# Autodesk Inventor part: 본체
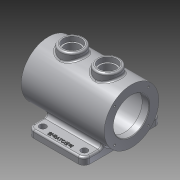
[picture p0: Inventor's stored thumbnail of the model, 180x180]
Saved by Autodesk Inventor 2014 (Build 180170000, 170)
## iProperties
Created: 2014-12
Part Number: 본체
Material: 알루미늄 6061
Document SubType Name: Modeling
Designer: Owner
Density: 2.71 g/cm^3
Appearance: 알루미늄 - 평지
Mass: 1293.91 g
Surface Area: 1040.15 cm^2
Volume: 477.456 cm^3
Author: Owner
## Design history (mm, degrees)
sketch "스케치1"
  geometry: L1 (-47.5, 65)-(47.5, 65); L2 (47.5, 65)-(47.5, -65); L3 (47.5, -65)-(-47.5, -65); L4 (-47.5, -65)-(-47.5, 65); 3 further points
  constraints: 8 end point, 2 midpoint, 2 parallel, 1 horizontal, 1 horizontal alignment, 1 perpendicular, 1 vertical alignment
  dimensions: "d0" = 95 distance of L1.start L1.end; "d1" = 130 distance of L1.end L2.end
extrude "돌출1" new body sketch "스케치1" distance "d2" = 12; taper "d3" = 0 deg
node "작업 평면1"
sketch "스케치2"
  geometry: L1 (0, 130)-(0, 0) reference; C1 r 46 at (-50, 65); 1 further point
  constraints: 1 centre point, 1 horizontal alignment
  dimensions: "d5" = 50 distance from line of L1 C1.centre; "d6" = 92 diameter of C1
extrude "돌출2" join sketch "스케치2" distance "d7" = 140; taper "d8" = 0 deg
node "작업 평면2"
sketch "스케치3"
  geometry: L1 (62.5, 46)-(62.5, -46) reference; C1 r 20 at (22.5, 0); C2 r 20 at (-37.5, 0); 1 further point
  constraints: 2 centre point, 2 horizontal alignment
  dimensions: "d10" = 40 distance from line of L1 C1.centre; "d11" = 60 distance of C2.centre C1.centre; "d12" = 40 diameter of C1; "d13" = 40 diameter of C2
extrude "돌출3" join sketch "스케치3" stored distance "d14" = 140; taper "d15" = 0 deg
hole "구멍1" diameter "d18" = 60; stored, may be unused: countersink angle "d22" = 90 deg, drill point angle "d24" = 0 deg; dims "d16" = 10, "d17" = 10, "d19" = 6, "d20" = 4, "d21" = 2, "d23" = 12
hole "구멍2" diameter "d27" = 75; stored, may be unused: countersink angle "d31" = 90 deg, drill point angle "d33" = 0 deg; dims "d25" = 10, "d26" = 10, "d28" = 6, "d29" = 4, "d30" = 2, "d32" = 116
hole "구멍3" diameter "d36" = 60; stored, may be unused: countersink angle "d40" = 90 deg, drill point angle "d42" = 0 deg; dims "d34" = 10, "d35" = 10, "d37" = 6, "d38" = 4, "d39" = 2, "d41" = 12
hole "구멍4" diameter "d45" = 30; stored, may be unused: countersink angle "d49" = 90 deg, drill point angle "d51" = 0 deg; dims "d43" = 10, "d44" = 10, "d46" = 6, "d47" = 4, "d48" = 2, "d50" = 8
hole "구멍5" diameter "d54" = 30; stored, may be unused: countersink angle "d58" = 90 deg, drill point angle "d60" = 0 deg; dims "d52" = 10, "d53" = 10, "d55" = 6, "d56" = 4, "d57" = 2, "d59" = 8
hole "구멍6" diameter "d63" = 25; stored, may be unused: countersink angle "d67" = 90 deg, drill point angle "d69" = 0 deg; dims "d61" = 10, "d62" = 10, "d64" = 6, "d65" = 4, "d66" = 2, "d68" = 8
hole "구멍7" diameter "d72" = 25; stored, may be unused: countersink angle "d76" = 90 deg, drill point angle "d78" = 0 deg; dims "d70" = 10, "d71" = 10, "d73" = 6, "d74" = 4, "d75" = 2, "d77" = 8
sketch "스케치4"
  geometry: L1 (0, 0)-(28.284, 28.284); L2 (0, 0)-(40, 0); C1 r 46 at (0, 0) reference; 2 further points
  constraints: 4 end point, 1 coincident, 1 equal length, 1 horizontal
  dimensions: "d79" = 40 distance of L1.start L1.end; "d80" = 45 deg angle of L2 L1
hole "구멍8" sketch "스케치4" at (28.284, 28.284) diameter "d81" = 3.242; stored, may be unused: countersink angle "d85" = 90 deg, drill point angle "d87" = 118 deg; dims "d82" = 8, "d83" = 4, "d84" = 2, "d86" = 10
sketch "스케치5"
  geometry: L1 (0, 0)-(28.284, 28.284); L2 (0, 0)-(40, 0); C1 r 46 at (0, 0) reference; 2 further points
  constraints: 4 end point, 1 coincident, 1 equal length, 1 horizontal
  dimensions: "d91" = 40 distance of L1.start L1.end; "d92" = 45 deg angle of L2 L1
hole "구멍9" sketch "스케치5" at (28.284, 28.284) diameter "d93" = 3.242; stored, may be unused: countersink angle "d97" = 90 deg, drill point angle "d99" = 118 deg; dims "d94" = 8, "d95" = 4, "d96" = 2, "d98" = 10
sketch "스케치6"
  geometry: L1 (47.5, -65)-(47.5, -25.923) reference; C1 r 5.5 at (-35, -52); C2 r 5.5 at (35, -52); C3 r 5.5 at (-35, 52); C4 r 5.5 at (35, 52); 1 further point
  constraints: 4 centre point, 3 equal radius, 2 horizontal alignment, 2 vertical alignment
  dimensions: "d103" = 70 distance of C2.centre C1.centre; "d104" = 104 distance of C2.centre C4.centre; "d105" = 52 vertical distance of C2.centre point (0, 0); "d106" = 12.5 distance from line of L1 C2.centre; "d107" = 11 diameter of C1
extrude "돌출4" cut sketch "스케치6" stored distance "d108" = 140; taper "d109" = 0 deg
fillet "모깎기1" dims "d110" = 10
fillet "모깎기2" dims "d111" = 5
fillet "모깎기3" dims "d112" = 3
fillet "모깎기4" dims "d113" = 3
sketch "스케치7"
  geometry: L1 (-37.5, -65)-(37.5, -65) reference; C1 r 5.5 at (-35, -52) reference; 2 further points
  constraints: 1 other
  dimensions: "d114" = 35 horizontal distance of point (0, -57) C1.centre; "d115" = 8 distance from line of L1 point (0, -57)
feature "엠보싱1" sketch "스케치7" dims "d0" = 95, "d1" = 130, "d15" = 0, "d116" = 1, "d117" = 0
chamfer "모따기1" distance "d118" = 1; stored, may be unused: second distance "d119" = 2, angle "d120" = 45 deg
fillet "모깎기5" dims "d121" = 3
node "솔리드1"
pattern_circular "원형 패턴1" dims angle "d89" = 360 deg
pattern_circular "원형 패턴2" dims angle "d101" = 360 deg
other parameters: "d4" = 15, "d9" = 106
